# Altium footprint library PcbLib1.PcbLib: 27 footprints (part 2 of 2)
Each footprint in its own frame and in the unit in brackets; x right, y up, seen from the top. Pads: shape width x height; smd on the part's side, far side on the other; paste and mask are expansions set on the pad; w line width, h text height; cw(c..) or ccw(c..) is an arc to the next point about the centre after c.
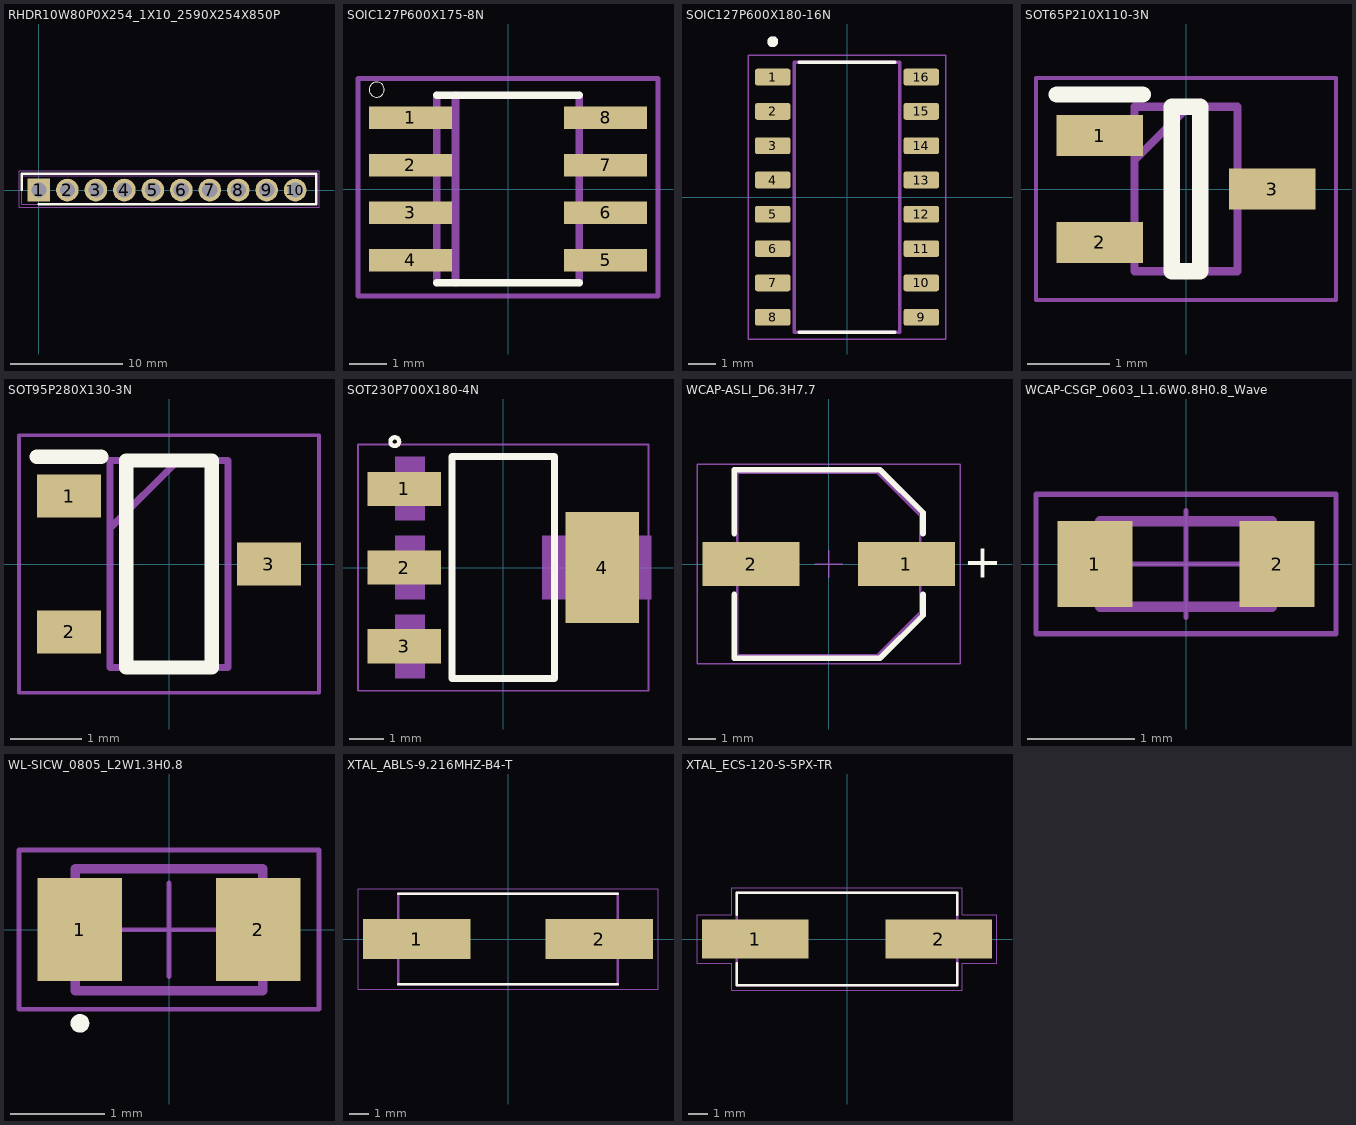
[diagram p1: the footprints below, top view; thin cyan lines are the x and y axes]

## RHDR10W80P0X254_1X10_2590X254X850P [mm]
pads (10):
  rect 2.025x2.025 hole 1.35: 1(0,0)
  round 2.025 hole 1.35: 2(2.54,0) 3(5.08,0) 4(7.62,0) 5(10.16,0) 6(12.7,0) 7(15.24,0) 8(17.78,0) 9(20.32,0) 10(22.86,0)
Top Overlay:
  lines w0.2: -1.52,0 -1.52,1.455 24.73,1.455 24.73,-1.27 0,-1.27
Mechanical 13:
  lines w0.1: -1.52,-1.27 24.73,-1.27 24.73,1.27 -1.52,1.27 -1.52,-1.27
Mechanical 15:
  lines w0.05: -1.77,-1.52 24.98,-1.52 24.98,1.705 -1.77,1.705 -1.77,-1.52
3D body "PPTC101LFBN-RC.stp": height 8.5, standoff -3.5, extent -1.52,-1.27 24.38,1.27

## SOIC127P600X175-8N [mm]
pads (8):
  rect 2.2x0.6 smd: 1(-2.6,1.905) 2(-2.6,0.635) 3(-2.6,-0.635) 4(-2.6,-1.905) 5(2.6,-1.905) 6(2.6,-0.635) 7(2.6,0.635) 8(2.6,1.905)
Top Overlay:
  circle w0: c-3.5,2.65 r0.2
  lines w0.203: -1.9,-2.5 1.9,-2.5 ; -1.9,2.5 1.9,2.5
Mechanical 13:
  region: -2.001,1.66 -3.1,1.66 -3.1,2.151 -2.001,2.151
  region: -2.003,0.388 -3.102,0.388 -3.102,0.883 -2.003,0.883
  region: -2.001,-0.881 -3.101,-0.881 -3.101,-0.389 -2.001,-0.389
  region: -2,-2.153 -3.103,-2.153 -3.103,-1.66 -2,-1.66
  region: 3.102,-2.15 2,-2.15 2,-1.662 3.102,-1.662
  region: 3.103,-0.879 2.001,-0.879 2.001,-0.392 3.103,-0.392
  region: 3.101,0.391 2.001,0.391 2.001,0.879 3.101,0.879
  region: 3.101,1.663 2.003,1.663 2.003,2.149 3.101,2.149
  lines w0.203: -1.9,-2.5 -1.9,2.5 ; -1.4,-2.5 -1.4,2.5 ; 1.9,-2.5 1.9,2.5
Mechanical 15:
  lines w0.127: -4,-2.85 4,-2.85 4,2.95 -4,2.95 -4,-2.85
3D body "step_temp.STEP": height 1.75, standoff 0, extent -3,-2.45 3,2.45

## SOIC127P600X180-16N [mm]
height 1.8
pads (16):
  rrect25% 1.31x0.62 smd: 1(-2.75,4.445) 2(-2.75,3.175) 3(-2.75,1.905) 4(-2.75,0.635) 5(-2.75,-0.635) 6(-2.75,-1.905) 7(-2.75,-3.175) 8(-2.75,-4.445) 9(2.75,-4.445) 10(2.75,-3.175) 11(2.75,-1.905) 12(2.75,-0.635) 13(2.75,0.635) 14(2.75,1.905) 15(2.75,3.175) 16(2.75,4.445)
Top Overlay:
  circle w0.2: c-2.75,5.755 r0.1
  lines w0.127: -1.775,-5 1.775,-5 ; -1.775,5 1.775,5
Mechanical 13:
  circle w0.2: c-2.75,5.755 r0.1
  lines w0.127: -1.95,-5 -1.95,5 1.95,5 1.95,-5 -1.95,-5
Mechanical 15:
  lines w0.05: -3.655,-5.25 -3.655,5.25 3.655,5.25 3.655,-5.25 -3.655,-5.25
3D body "step_temp.STEP": height 1.8, standoff 0, extent -3,-5 3,5

## SOT65P210X110-3N [mm]
pads (3):
  rect 1.05x0.5 smd: 1(-1.05,0.65) 2(-1.05,-0.65) 3(1.05,0)
Top Overlay:
  lines w0.2: -1.575,1.15 -0.525,1.15 ; -0.175,-1 -0.175,1 0.175,1 0.175,-1 -0.175,-1
Mechanical 15:
  lines w0.1: -0.625,0.35 0.025,1 ; -0.625,-1 -0.625,1 0.625,1 0.625,-1 -0.625,-1
Mechanical 20:
  lines w0.05: -1.825,-1.35 -1.825,1.35 1.825,1.35 1.825,-1.35 -1.825,-1.35
3D body "SI1317DL-T1-GE3.stp": height 1.1, standoff 0, extent -1.05,-1 1.05,1

## SOT95P280X130-3N [mm]
pads (3):
  rect 0.9x0.6 smd: 1(-1.4,0.95) 2(-1.4,-0.95) 3(1.4,0)
Top Overlay:
  lines w0.2: -1.85,1.5 -0.95,1.5 ; -0.6,-1.45 -0.6,1.45 0.6,1.45 0.6,-1.45 -0.6,-1.45
Mechanical 15:
  lines w0.1: -0.825,0.5 0.125,1.45 ; -0.825,-1.45 -0.825,1.45 0.825,1.45 0.825,-1.45 -0.825,-1.45
Mechanical 20:
  lines w0.05: -2.1,-1.8 -2.1,1.8 2.1,1.8 2.1,-1.8 -2.1,-1.8
3D body "XC6206P332MR-G.stp": height 1.3, standoff 0, extent -1.4,-1.45 1.4,1.45

## SOT230P700X180-4N [mm]
pads (4):
  rect 2.15x1 smd: 1(-2.9,2.3) 2(-2.9,0) 3(-2.9,-2.3)
  rect 2.15x3.25 smd: 4(2.9,0)
Top Overlay:
  circle w0.127: c-3.175,3.683 r0.127
  lines w0.203: -1.5,-3.25 -1.5,3.25 1.5,3.25 1.5,-3.25 -1.5,-3.25
Mechanical 13:
  region: -2.299,-3.241 -3.165,-3.241 -3.165,-1.384 -2.299,-1.384
  region: -2.299,1.387 -3.167,1.387 -3.167,3.238 -2.299,3.238
  region: -2.299,-0.928 -3.164,-0.928 -3.164,0.927 -2.299,0.927
  region: 4.331,-0.929 1.132,-0.929 1.132,0.927 4.331,0.927
  region: -2.299,-3.242 -3.165,-3.242 -3.165,-1.384 -2.299,-1.384
  region: -2.299,1.386 -3.166,1.386 -3.166,3.238 -2.299,3.238
  region: -2.299,-0.927 -3.164,-0.927 -3.164,0.927 -2.299,0.927
  region: 4.331,-0.929 1.132,-0.929 1.132,0.927 4.331,0.927
Mechanical 15:
  lines w0.05: -4.25,-3.6 -4.25,3.6 4.25,3.6 4.25,-3.6 -4.25,-3.6
3D body "NCP1117ST50T3G.STEP": height 1.81, standoff -0.59, extent -3.486,-3.25 3.641,3.25

## WCAP-ASLI_D6.3H7.7 [mm] "Aluminium Electrolytic V-Chip SMT Capacitors, 6.3x7.7mm"
height 7.7
pads (2):
  rect 3.5x1.6 smd: 1(2.8,0) 2(-2.8,0)
Top Overlay:
  lines w0.2: -3.4,-1.1 -3.4,-3.4 1.85,-3.4 3.4,-1.85 3.4,-1.1 ; -3.4,1.1 -3.4,3.4 1.85,3.4 3.4,1.85 3.4,1.1
  text "+" at 4.85,-0.5 h1.22
Top 3D Body:
  lines w0.1: -3.3,-3.3 1.75,-3.3 3.3,-1.75 3.3,1.75 1.75,3.3 -3.3,3.3 -3.3,-3.3
Top Courtyard:
  lines w0.05: -0.5,0 0.5,0 ; 0,-0.5 0,0.5 ; -4.75,-3.6 -4.75,3.6 4.75,3.6 4.75,-3.6 -4.75,-3.6
Top Designator:
  text ".Designator" at -7.498,-0.5 h1.5
Top Component Outline:
  lines w0.1: -3.3,-3.3 1.75,-3.3 3.3,-1.75 3.3,1.75 1.75,3.3 -3.3,3.3 -3.3,-3.3
3D body "6.3x7.7x2.2.stp": height 7.7, standoff 0, extent -3.65,-3.3 3.65,3.3

## WCAP-CSGP_0603_L1.6W0.8H0.8_Wave [mm] "Ceramic Capacitors, 0603, body 1.6x0.8mm"
height 0.8
pads (2):
  rect 0.7x0.8 smd: 1(-0.85,0) 2(0.85,0)
Top Courtyard:
  lines w0.05: -1.4,-0.65 -1.4,0.65 1.4,0.65 1.4,-0.65 -1.4,-0.65
Top Designator:
  text ".Designator" at -2.499,-0.167 h0.5
Top Component Outline:
  lines w0.1: -0.8,-0.4 -0.8,0.4 0.8,0.4 0.8,-0.4 -0.8,-0.4
Top Component Center:
  lines w0.05: -0.5,0 0.5,0 ; 0,-0.5 0,0.5
3D body "CAPC1608X08N.step": height 0.8, standoff 0, extent -0.8,-0.4 0.8,0.4

## WL-SICW_0805_L2W1.3H0.8 [mm] "SMT Infrared Chip LED Waterclear, body 2x1.3mm"
height 0.8
pads (2):
  rect 0.9x1.1 smd: 1(-0.95,0) 2(0.95,0)
Top Overlay:
  circle w0.1: c-0.95,-1 r0.05
Top 3D Body:
  circle w0.05: c-0.75,-0.4 r0.1
  lines w0.1: -1,-0.65 -1,0.65 1,0.65 1,-0.65 -1,-0.65
Top Courtyard:
  lines w0.05: -0.5,0 0.5,0 ; 0,-0.5 0,0.5 ; -1.6,-0.85 1.6,-0.85 1.6,0.85 -1.6,0.85 -1.6,-0.85
Top Designator:
  text ".Designator" at -2.499,-0.167 h0.5
Top Component Outline:
  circle w0.05: c-0.75,-0.4 r0.1
  lines w0.1: -1,-0.65 1,-0.65 1,0.65 -1,0.65 -1,-0.65
3D body "15408085BA400.stp": height 0.8, standoff 0, extent -1,-0.65 1,0.65

## XTAL_ABLS-9.216MHZ-B4-T [mm]
height 4.2
pads (2):
  rect 5.6x2.1 smd: 1(-4.75,0) 2(4.75,0)
Top Overlay:
  lines w0.127: -5.7,-2.35 5.7,-2.35 ; -5.7,2.35 5.7,2.35
Mechanical 13:
  lines w0.127: -5.7,-2.35 -5.7,2.35 5.7,2.35 5.7,-2.35 -5.7,-2.35
Mechanical 15:
  lines w0.05: -7.8,-2.6 -7.8,2.6 7.8,2.6 7.8,-2.6 -7.8,-2.6
3D body "step_temp.STEP": height 4.06, standoff -0.1, extent -6.35,-2.349 6.35,2.349

## XTAL_ECS-120-S-5PX-TR [mm]
pads (2):
  rect 5.5x2 smd: 1(-4.75,0) 2(4.75,0)
Top Overlay:
  lines w0.127: -5.7,-1.254 -5.7,-2.4 5.7,-2.4 5.7,-1.254 ; -5.7,1.254 -5.7,2.4 5.7,2.4 5.7,1.254
Mechanical 13:
  lines w0.127: -5.7,-2.4 -5.7,2.4 5.7,2.4 5.7,-2.4 -5.7,-2.4
Mechanical 15:
  lines w0.05: -7.75,-1.25 -5.95,-1.25 -5.95,-2.65 5.95,-2.65 5.95,-1.25 7.75,-1.25 7.75,1.25 5.95,1.25 5.95,2.65 -5.95,2.65 -5.95,1.25 -7.75,1.25 -7.75,-1.25
3D body "ECS-120-S-5PX-TR.STEP": height 4.31, standoff 0.01, extent -6.6,-2.39 6.6,2.41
